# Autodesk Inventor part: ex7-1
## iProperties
Author: Administrator
Revision Number: A
Created: 2001-03
Part Number: ex7-1
Document SubType Name: Modeling
Designer: Administrator
Control State: 0
Master: False
Checked Out: False
PropertySet Name: Design Tracking Control
Shininess: 20.0
PropertySet Name: _Private Model Information
Density: 0.0
Volumn: 0.0
Area: 0.0
PropertySet Name: Model Information
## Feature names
1. Revolution1
2. Fillet1
